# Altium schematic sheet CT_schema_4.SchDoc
size 186 x 134 mm
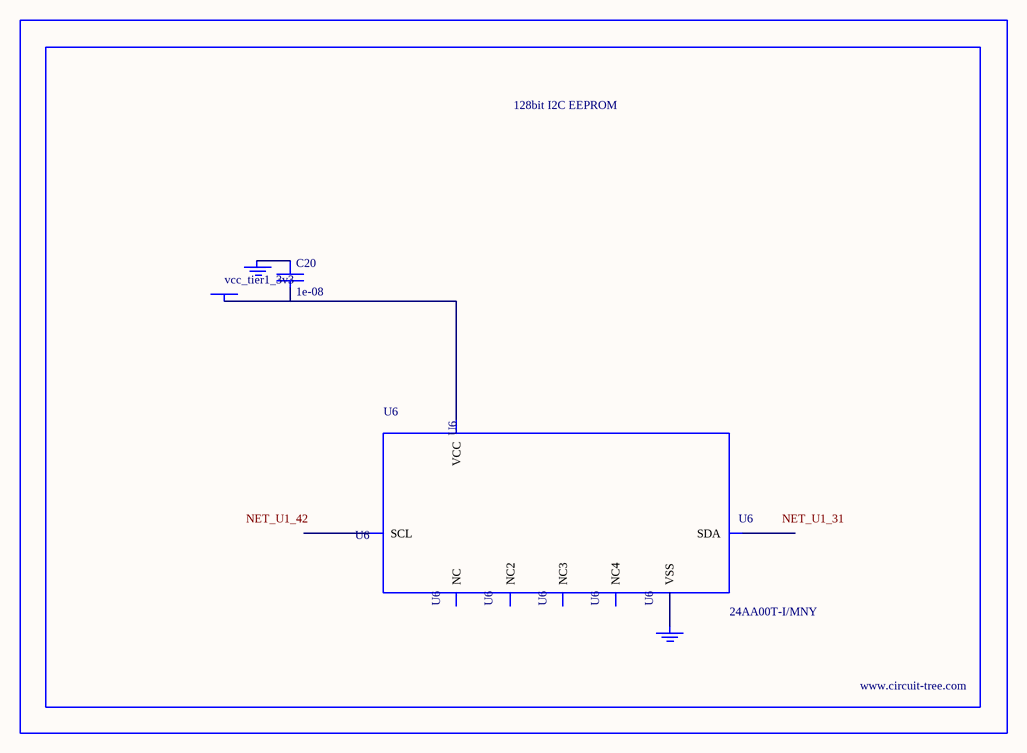
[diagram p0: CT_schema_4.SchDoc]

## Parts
BORDER3  (no value)
C20  1e-08  [C0402]
GND_INSTANCE_3_0  (no value)
GND_INSTANCE_3_1  (no value)
POWER_INSTANCE_3_0  vcc_tier1_3v3
U6  24AA00T-I/MNY  [TDFN-8/6MM]

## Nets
NetC20_1: C20.1 GND_INSTANCE_3_0.0(GND)
NetC20_2: C20.2 POWER_INSTANCE_3_0.0(PWR) U6.8(VCC)
NetGND_INSTANCE_3_1_0: GND_INSTANCE_3_1.0(GND) U6.4(VSS)

Not connected (* = marked no-connect by the designer): U6 1(NC) 2(NC2) 3(NC3) 5(SDA) 6(SCL) 7(NC4)

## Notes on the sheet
- Labels drawn without touching a wire or pin: NET_U1_31, NET_U1_42

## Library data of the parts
BORDER3 = BORDER_PAGE3
C20 = C0402C103K3RAC
GND_INSTANCE_3_0 GND_INSTANCE_3_1 = GND
POWER_INSTANCE_3_0 = PWR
